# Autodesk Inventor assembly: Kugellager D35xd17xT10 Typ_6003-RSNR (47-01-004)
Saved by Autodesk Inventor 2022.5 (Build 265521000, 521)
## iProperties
Created: 2024-12
Part Number: Kugellager D35xd17xT10 Typ_6003-RSNR (47-01-004)
Document SubType Name: Assembly
Designer: AdminForWorker
Title: Kugellager D35xd17xT10 Typ_6003-RSNR (47-01-004) v1
Author: AdminForWorker
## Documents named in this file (6)
- c:\worker\convert-fusion-r05-cosv3\tmp\job-1\110\temp\files\515e27a0-2939-429c-b540-42badd8f7cfa\d53f5020-5dc5-462a-a43d-d404163f0128.zip.iam
- c:\worker\convert-fusion-r05-cosv3\tmp\job-1\110\temp\files\515e27a0-2939-429c-b540-42badd8f7cfa\6003-2Z_InnerRing.ipt
- c:\worker\convert-fusion-r05-cosv3\tmp\job-1\110\temp\files\515e27a0-2939-429c-b540-42badd8f7cfa\6003-2Z_Ball.ipt
- c:\worker\convert-fusion-r05-cosv3\tmp\job-1\110\temp\files\515e27a0-2939-429c-b540-42badd8f7cfa\6003-RSNR_Outer Ring.ipt
- c:\worker\convert-fusion-r05-cosv3\tmp\job-1\110\temp\files\515e27a0-2939-429c-b540-42badd8f7cfa\6003-RSNR_Shield schwarz.ipt
- c:\worker\convert-fusion-r05-cosv3\tmp\job-1\110\temp\files\515e27a0-2939-429c-b540-42badd8f7cfa\6003-RSNR_Sprengring.ipt
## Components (16 placed, 5 different names)
1. 6003-2Z_InnerRing:1
2. 6003-2Z_Ball:1
3. 6003-2Z_Ball:2
4. 6003-2Z_Ball:3
5. 6003-2Z_Ball:4
6. 6003-2Z_Ball:5
7. 6003-2Z_Ball:6
8. 6003-2Z_Ball:7
9. 6003-2Z_Ball:8
10. 6003-2Z_Ball:9
11. 6003-2Z_Ball:10
12. 6003-2Z_Ball:11
13. 6003-RSNR_Outer Ring:1
14. 6003-RSNR_Shield schwarz:1
15. 6003-RSNR_Shield schwarz:2
16. 6003-RSNR_Sprengring:1
